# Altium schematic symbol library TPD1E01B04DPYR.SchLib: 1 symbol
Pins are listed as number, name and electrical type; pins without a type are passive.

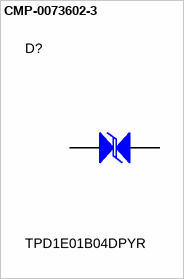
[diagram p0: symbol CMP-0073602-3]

## CMP-0073602-3
designator D?, comment TPD1E01B04DPYR
1-Channel ESD Protection Diode for USB Type-C and Thunderbolt 3, DPY0002A (X1SON-2); Alternate Manufacturer: Texas Instruments; Alternate PartNumber: TPD1E01B04DPYT; CompType: TVS Diode; AEC Category: Q200; SizeArea_mm2: 0.6; CompType: IC; SizeAreaWB_mm2: 3.2; SizeZ_mm: 0.45; Rating: Catalog; SizeX_mm: 1.0
footprint DPY0002A (X1SON-2)
pins: 1, 2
